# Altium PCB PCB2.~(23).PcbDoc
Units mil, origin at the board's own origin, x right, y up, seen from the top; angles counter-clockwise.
Board outline 7005 x 4320 mil, 2 copper layers (Top Layer, Bottom Layer); 81 components, 33 nets, 200 pads, 0 vias.
Unrouted connection lines stored in the file: 56.
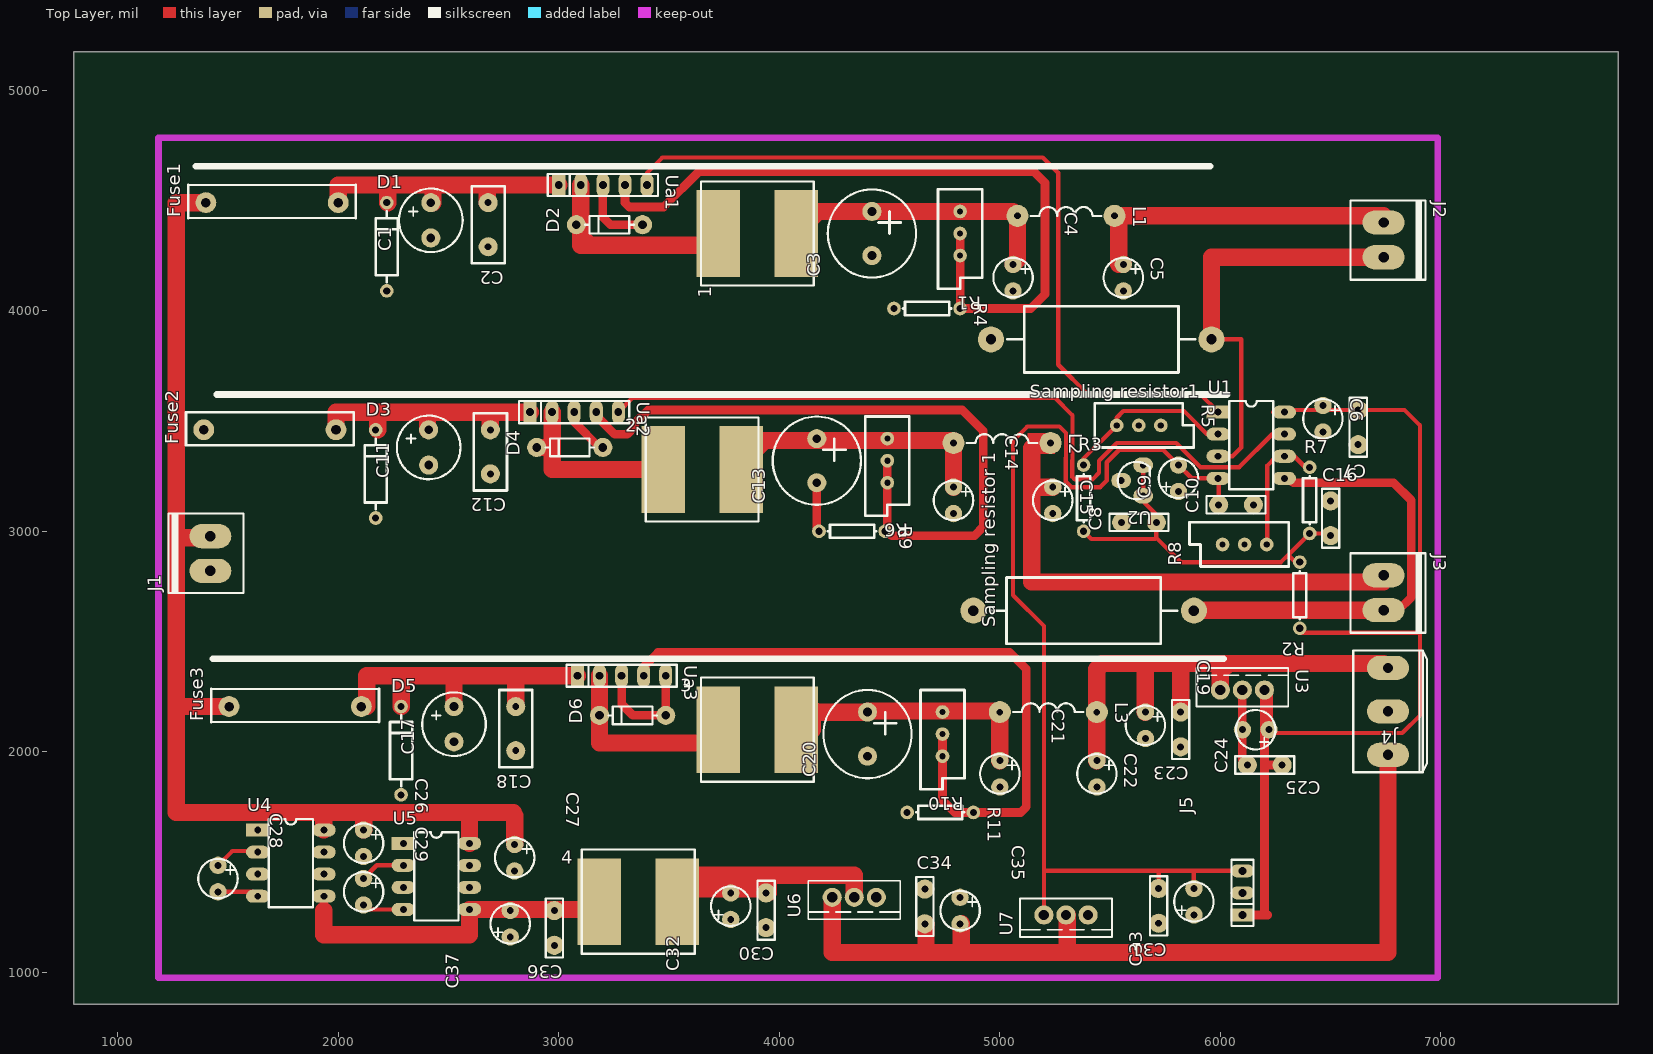
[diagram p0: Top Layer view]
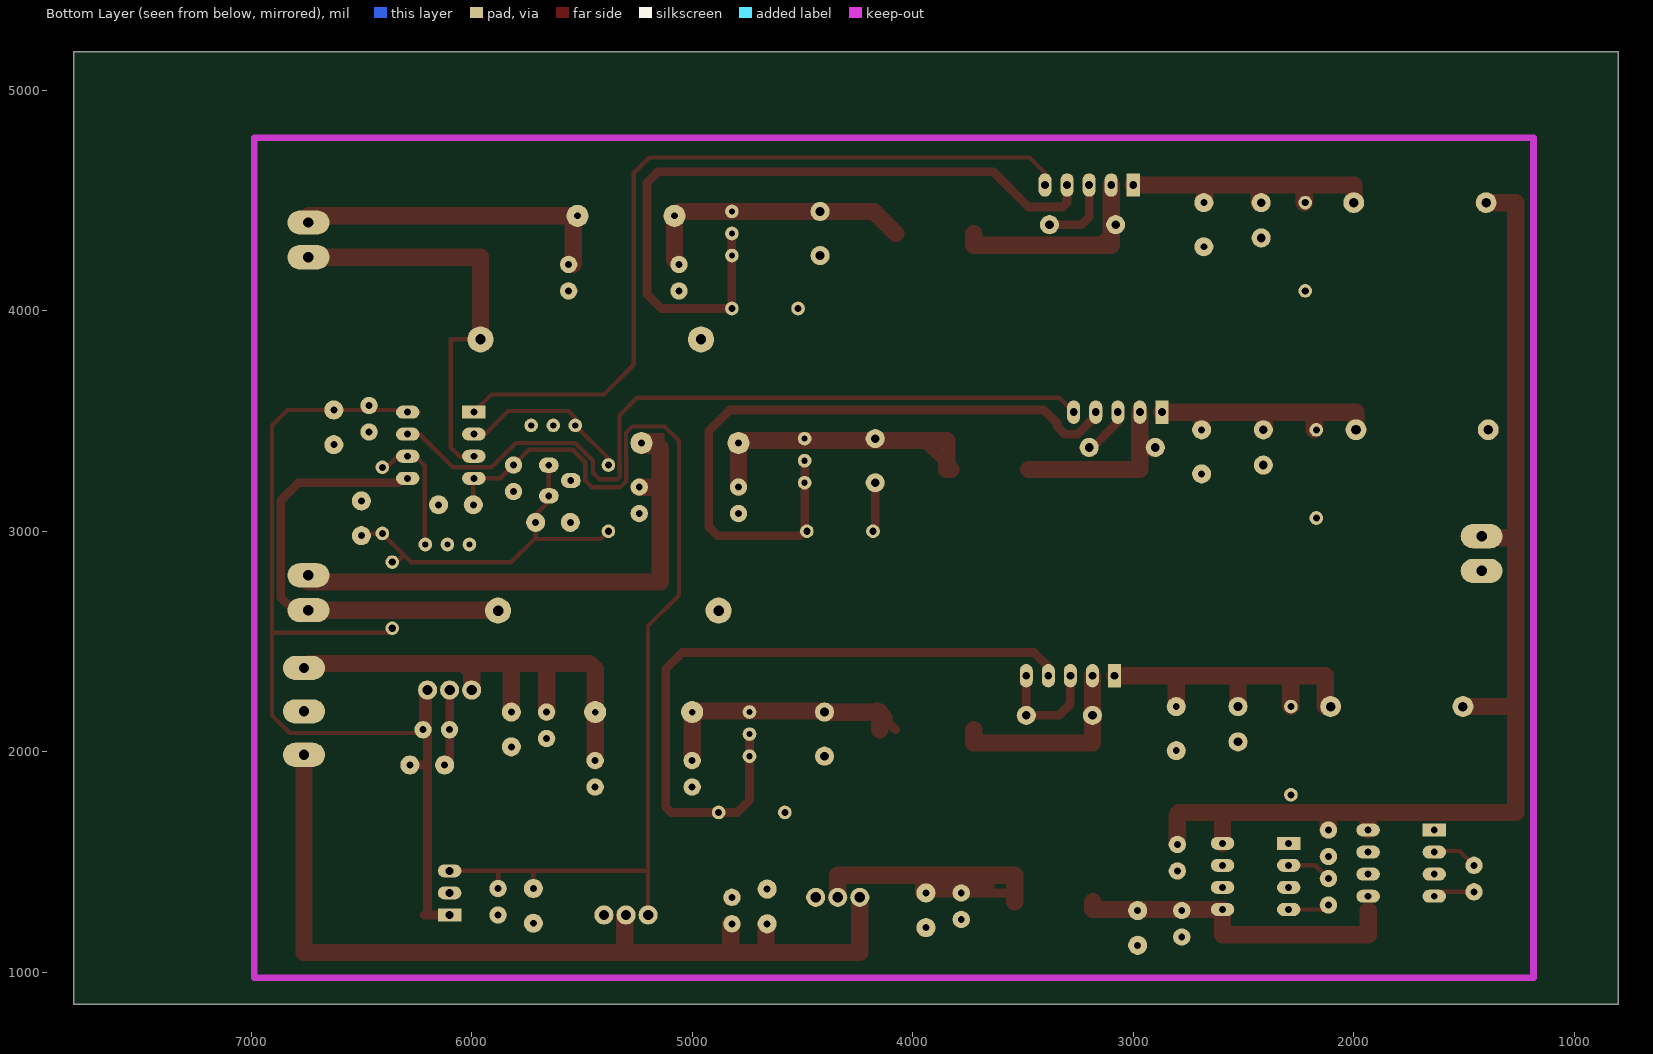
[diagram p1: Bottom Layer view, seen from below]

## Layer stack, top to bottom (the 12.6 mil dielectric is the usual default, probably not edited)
Top Layer: signal copper 1.4
Dielectric: dielectric 12.6, FR-4, Dk 4.8
Bottom Layer: signal copper 1.4

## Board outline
800,5175 800,855 3655,855 7805,855 7805,1010 7805,5175 800,5175

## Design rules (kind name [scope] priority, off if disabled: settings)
Clearance [All] p1: gap=10
PolygonConnect [All] p1: connectstyle=Relief reliefconductorwidth=10 reliefentries=4 polygonreliefangle="90 Angle"
RoutingVias [All] p1: holewidth=28 width=50 viastyle="Through Hole" minholewidth=28 minwidth=50 maxholewidth=28 maxwidth=50
SilkscreenOverComponentPads [All] p1 off: minsilkscreentomaskgap=10
SolderMaskExpansion [All] p1: expansion=4
TestPointUsage [All] p1: valid=0 allowmultiple=FALSE
Testpoint [All] p1: side=15 testpointundercomponent=TRUE minsize=40 maxsize=100 preferedsize=60 minholesize=0 maxholesize=40 preferedholesize=32 testpointgrid=1 style=1023 order=0123456789
Width Width_1 [All] p1: maxlimit=78.74 minlimit=10 preferedwidth=10 toplayer_minwidth=19.68 toplayer_prefwidth=39.37 bottomlayer_minwidth=39.37 bottomlayer_maxwidth=39.37 bottomlayer_prefwidth=39.37 minimp=50.000000 maximp=50.000000 favimp=50.000000
Width [OnLayer('Top Layer')] p2: maxlimit=47.24 minlimit=10 preferedwidth=10 toplayer_minwidth=19.68 toplayer_prefwidth=39.37 bottomlayer_maxwidth=10 minimp=50.000000 maximp=50.000000 favimp=50.000000
23 further rules are at their usual default settings.

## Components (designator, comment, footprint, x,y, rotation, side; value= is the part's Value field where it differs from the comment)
1 "330uh" L 3920,4350 r90 top
2 "330uh" L 3670,3280 r90 top
3 "330uh" L 3920,2100 r90 top
4 "330uh" L 3380,1320 r90 top
C1 "1000uf" RB2 2400,4490 r90 top
C2 "104" RAD0.2 2680,4490 r270 top
C3 "2000uh" RB3 4420,4450 r90 top
C4 "100uf" RB1 5060,4150 r270 top
C5 "100uf" RB1 5560,4150 r270 top
C6 "10uf" RB1 6465,3510 r270 top
C7 "104" RAD0.15 6625,3550 r270 top
C8 "104" RAD0.15 5710,3040 r180 top
C9 "10uf" RB1 5810,3240 r90 top
C10 "104" RAD0.15 6150,3120 r180 top
C11 "1000uf" RB2 2390,3460 r90 top
C12 "104" RAD0.2 2690,3460 r270 top
C13 "2000uf" RB3 4170,3420 r90 top
C14 "100uf3" RB1 4790,3140 r270 top
C15 "100" RB1 5240,3140 r270 top
C16 "104" RAD0.15 6500,2980 r90 top
C17 "1000uf" RB2 2505,2205 r90 top
C18 "104" RAD0.2 2805,2205 r270 top
C19 "10uf" RB1 5660,2120 r270 top
C20 "2000uf" RB3 4400,2180 r90 top
C21 "100uf" RB1 5000,1900 r270 top
C22 "100uf" RB1 5440,1900 r270 top
C23 "104" RAD0.15 5820,2180 r270 top
C24 "104" RAD0.15 6280,1940 r180 top
C25 "10uf" RB1 6160,2100 r180 top
C26 "100uf" RB1 2115,1585 r270 top
C27 "100uf" RB1 2800,1520 r270 top
C28 "10uf" RB1 1455,1425 r270 top
C29 "10uf" RB1 2115,1365 r270 top
C30 "104" RAD0.15 3940,1360 r270 top
C31 "104" RAD0.15 5720,1380 r270 top
C32 "10uf" RB1 3780,1300 r90 top
C33 "10uf" RB1 5880,1320 r90 top
C34 "104" RAD0.15 4660,1220 r90 top
C35 "10uf" RB1 4820,1280 r270 top
C36 "104" RAD0.15 2980,1280 r270 top
C37 "10uf" RB1 2780,1220 r90 top
D1 "IN4007" DIODE0.4 2220,4090 r90 top
D2 "MBR360" DIODE0.2 3260,4390 r180 top
D3 "IN4007" DIODE0.4 2170,3060 r90 top
D4 "MBR360" DIODE0.2 3080,3380 r180 top
D5 "IN4007" DIODE0.4 2285,1805 r90 top
D6 "MBR360" DIODE0.2 3365,2165 r180 top
Fuse1 "4A" RAD0.5 1700,4490 r180 top
Fuse2 "4A" RAD0.5 1690,3460 r180 top
Fuse3 "4A" RAD0.5 1805,2205 r180 top
J1 "CON2" BCON2 1420,2820 r90 top
J2 "CON2" BCON2 6740,4400 r270 top
J3 "CON2" BCON2 6740,2800 r270 top
J4 "CON3" BCON3 6760,2380 r270 top
J5 "CON3" sip-3 6100,1260 r90 top
L1 "20uh" LHF440 5080,4430 r0 top
L2 "20uh" LHF440 4790,3400 r0 top
L3 "20uh" LHF440 5000,2180 r0 top
R1 "50K" VR5 4820,4450 r270 top
R2 "1k" AXIAL0.3 6360,2860 r270 top
R3 "1k" AXIAL0.3 5380,3000 r90 top
R4 "1.21K" AXIAL0.3 4520,4010 r0 top
R5 "5k" VR5 5530,3480 r0 top
R6 "50k" VR5 4490,3420 r270 top
R7 "1k" AXIAL0.3 6405,2990 r90 top
R8 "5k" VR5 6210,2940 r180 top
R9 "1.21K" AXIAL0.3 4180,3000 r0 top
R10 "50k" VR5 4740,2180 r270 top
R11 "1.21k" AXIAL0.3 4580,1725 r0 top
"Sampling resistor1" "0.1" AXIAL1.0 5960,3870 r180 top
"Sampling resistor 1" "0.1   100w" AXIAL1.0 5880,2640 r180 top
U1 "OPA2228" DIP-8 5990,3540 r0 top
U2 "TL431" TO92B 5650,3160 r180 top
U3 "7805" TO257V 6000,2280 r0 top
U4 "ICL7662" DIP-8 1635,1645 r0 top
U5 "ICL7662" DIP-8 2295,1585 r0 top
U6 "7915" TO257V 4440,1340 r180 top
U7 "7905" TO257V 5400,1260 r180 top
Ua1 "LM2596HVADJ" SIP-5 3000,4570 r0 top
Ua2 "LM2596HVADJ" SIP-5 2870,3540 r0 top
Ua3 "LM2596HVADJ" SIP-5 3085,2345 r0 top

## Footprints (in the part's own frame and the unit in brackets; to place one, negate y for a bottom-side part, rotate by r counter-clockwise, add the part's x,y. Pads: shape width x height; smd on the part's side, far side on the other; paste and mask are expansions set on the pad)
AXIAL0.3 [mil]
  round 62 hole 32: 1(0,0) 2(300,0)
  silkscreen extent 41,-30 259,30
AXIAL1.0 [mm]
  round 3 hole 1.2: 1(0,0) 2(25.4,0)
  silkscreen extent 1.91,-3.81 23.49,3.81
BCON2 [mil]
  oval 110x190 hole 47.24: 1(0,0) 2(157.48,0)
  silkscreen extent -100,-150 260,190
BCON3 [mil]
  oval 110x190 hole 47.24: 1(0,0) 2(196.85,0) 3(393.7,0)
  silkscreen extent -79,-157 472,177
DIODE0.2 [mm]
  round 2.2 hole 1: 1(-3.048,0) 2(4.572,0)
  silkscreen extent -2.03,-1.02 3.56,1.02
DIODE0.4 [mil]
  round 62 hole 32: 1(0,0) 2(400,0)
  silkscreen extent 40,-50 360,50
DIP-8 [mm]
  rect 2.7x1.5 hole 0.8: 1(0,0)
  oval 2.7x1.5 hole 0.8: 2(0,-2.54) 3(0,-5.08) 4(0,-7.62) 5(7.62,-7.62) 6(7.62,-5.08) 7(7.62,-2.54) 8(7.62,0)
  silkscreen extent 1.27,-8.89 6.35,1.27
L [mm]
  rect 10x5 smd: 1(0,5) 2(0,-4)
  silkscreen extent -6,-6 6,7
LHF440 [mil]
  round 100 hole 30: 1(0,0) 2(440,0)
  silkscreen extent 60,0 380,40
RAD0.2 [mm]
  round 2.2 hole 0.8: 1(0,0) 2(5.08,0)
  silkscreen extent -1.91,-1.91 6.98,1.91
RAD0.5 [mm]
  round 2.4 hole 1.1: 1(-7.62,0) 2(7.62,0)
  silkscreen extent -9.65,-2.03 9.65,1.78
RAD0.15 [mm]
  round 2.2 hole 0.8: 1(0,0) 2(4,0)
  silkscreen extent -1.4,-1 5.4,1
RB1 [mm]
  round 2 hole 0.8: 1(-1.524,0) 2(1.524,0)
  silkscreen extent -2.27,-2.27 2.27,2.27
RB2 [mm]
  round 2.2 hole 1: 1(0,-0.508) 2(-4.064,-0.508)
  silkscreen extent -5.69,-4.17 1.63,3.15
RB3 [mm]
  round 2.2 hole 1: 1(0,0) 2(-5.08,0)
  silkscreen extent -7.62,-5.08 2.54,5.08
sip-3 [mm]
  rect 1.5x2.7 hole 0.9: 1(0,0)
  oval 1.5x2.7 hole 0.9: 2(2.54,0) 3(5.08,0)
  silkscreen extent -1.27,-1.27 6.35,1.27
SIP-5 [mm]
  rect 1.5x2.7 hole 0.9: 1(0,0)
  oval 1.5x2.7 hole 0.9: 2(2.54,0) 3(5.08,0) 4(7.62,0) 5(10.16,0)
  silkscreen extent -1.27,-1.27 11.43,1.27
TO92B [mil]
  oval 90x70 hole 30: 1(0,0) 2(100,-70) 3(0,-140)
  silkscreen extent -30,-155 115,15
TO257V [mm]
  round 2.2 hole 1.2: 1(0,0) 2(2.54,0) 3(5.08,0)
  silkscreen extent -2.75,-1.91 7.83,2.54
VR5 [mil]
  round 62 hole 28: 1(0,0) 2(100,0) 3(200,0)
  silkscreen extent -100,-100 350,100

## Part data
1 2 3 4: library part INDUCTOR2
C1 C3 C4 C5 C6 C9 C11 C13 C14 C15 C17 C19 C20 C21 C22 C25 C26 C27 C28 C29 C32 C33 C35 C37: library part CAP3
C2 C7 C8 C10 C12 C16 C18 C23 C24 C30 C31 C34 C36: library part CAP1
D1 D2 D3 D4 D5 D6: library part DIODE
Fuse1 Fuse2 Fuse3: library part FUSE1, "Fuse"
J1 J2 J3 J4 J5: "Connector"
L1 L2 L3: library part INDUCTOR
R1 R5 R6 R8 R10: library part RPOT2, "Potentiometer"
R2 R3 R4 R7 R9 R11 "Sampling resistor1" "Sampling resistor 1": library part RES
U1: library part NE5532
U2: "Programmable Voltage Reference"
U3: library part 78**
U6 U7: library part 79**
Ua1 Ua2 Ua3: library part LM2596T-5.0, "Simple Switcher Power Converter 150 kHz 3A Step Down Voltage Regulator"

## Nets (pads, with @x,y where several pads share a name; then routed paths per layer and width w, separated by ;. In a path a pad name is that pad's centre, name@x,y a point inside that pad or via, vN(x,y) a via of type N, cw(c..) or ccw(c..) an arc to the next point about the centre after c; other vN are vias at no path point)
"5V 3A": C5.1 J2.1 L1.2 | length 2868.3
  Top Layer w39.37: L1.2 J2.1@6710,4430 ; L1.2@5540,4410 5540,4230 C5.1
  Top Layer w78.74: C5.1 5540,4210 5540,4430 6740,4430 J2.1
"8V 3A": C15.1 J3.1 L2.2 | length 2326.7
  Top Layer w78.74: 5145,3376.71 5145,3200 ; C15.1 5145,3200 ; J3.1 6740,2770 5145,2770 5145,3200
+5V: C6.1 C7.1 C24.1 C25.1 J5.1 R2.2 U1.8 U3.3 | length 4661.6
  Top Layer w19.68: C25.1 6235,2085 6825,2085 6905,2165 6905,3480 6835,3550 C7.1 U1.8@6300,3550 ; U1.8@6240,3540 U1.8 ; R2.2@6360,2540 6895,2540
  Top Layer w39.37: J5.1 6200,1260 ; 6215,1260 6200,1260 ; C25.1 6220,2260 U3.3 6200,1940 ; C24.1 6200,1940 ; 6200,1260 6200,1940
+15V: C19.1 C22.1 C23.1 J4.1 L3.2 U3.1 | length 2293.1
  Top Layer w78.74: C22.1 L3.2 5440,2375 5465,2400 6035,2400 ; C19.1 5660,2370 ; C23.1 5820,2395 ; U3.1 6000,2365 6035,2400 ; J4.1 6740,2400 6035,2400
-5V: C9.2 C10.2 C31.1 C33.2 J5.3 U1.4 U7.3 | length 4801.9
  Top Layer w19.68: U7.3@5200,1300 U7.3 5200,1460 ; C31.1 5720,1460 ; C33.2 5880,1460 ; C10.2 5992.52,3237.48 U1.4 5870,3240 C9.2 5740,3370 5541.98,3370 5485,3313.02 5485,3230 5455,3200 5325,3200 5299.47,3225.53 5299.47,3333.36 5299.84,3333.73 5299.84,3445.16 5270,3475 5125,3475 5060,3410 5060,2710 5200,2570 5200,1460 ; J5.3 5880,1460 ; 5200,1460 5720,1460 ; 5720,1460 5880,1460
-15V: C34.1 C35.2 J4.3 U6.3 U7.2 | length 4370.4
  Top Layer w39.37: 4660,1145 C34.1 ; 4820,1145 C35.2 ; U7.2 5305,1255 5310,1250 5310,1140
  Top Layer w78.74: U6.3 4240,1090 4665,1090 ; C34.1@4665,1220 4665,1090 ; C35.2@4825,1220 4825,1090 ; U7.2@5305,1260 5305,1255 5305,1090 ; J4.3 6760,1090 5305,1090 ; 4665,1090 4825,1090 ; 4825,1090 5305,1090
FB5V: U1.1 Ua1.5 | length 3662
  Top Layer w19.68: Ua1.5 3400,4625 3470,4695 5195,4695 5265,4625 5265,3755 5400,3620 5910,3620 U1.1
FB8V: U1.7 Ua2.5 | length 3572.8
  Top Layer w19.68: Ua2.5 3335,3605 5250,3605 5329.53,3525.47 5329.53,3321.43 5329.16,3321.06 5329.16,3245.84 5340,3235 5420,3235 5450,3265 5450,3320 5530,3400 5800,3400 5910,3290 6085,3290 6235,3440 U1.7
GND: "Sampling resistor1.2" "Sampling resistor 1.2" C1.2 C2.2 C3.2 C4.2 C5.2 C6.2 C7.2 C8.2 C9.1 C10.1 C11.2 C12.2 C13.2 C14.2 C15.2 C16.2 C17.2 C18.2 C19.2 C20.2 C21.2 C22.2 C23.2 C24.2 C25.2 C26.2 C27.2 C30.2 C31.2 C32.1 C33.1 C34.2 C35.1 C36.2 C37.1 D1.1 D2.1 D3.1 D4.1 D5.1 D6.1 J1.1 J4.2 J5.2 R4.1 R5.2 R5.3 R8.2 R8.3 R9.1 R11.1 U2.2 U3.2 U4.3 U5.3 U6.1 U7.1 Ua1.3 Ua2.3 Ua3.3 Ua3.5 | length 1662.2
  Top Layer w39.37: Ua2.3 3070,3495 3185,3380 D4.1@3210,3380 ; Ua1.3 3200,4425 3235,4390 D2.1 ; Ua3.3 3285,2215 3335,2165 D6.1 Ua3.5 ; R9.1@4170,3010 C13.2 ; U3.2 C25.2 6100,1962.52 C24.2
Net1_1: 1.1 D2.2 Ua1.2 | length 1605.2
  Top Layer w39.37: D2.2@3100,4365 3147.99,4317.01 3690.16,4317.01 1.1
  Top Layer w78.74: Ua1.2 3100,4297.32 3723.15,4297.32 1.1
Net1_2: 1.2 C3.1 C4.1 L1.1 R1.1 | length 1280.5
  Top Layer w78.74: 1.2 4177.48,4450 C3.1 R1.1 5060,4450 L1.1 5080,4230 C4.1
Net2_1: 2.1 D4.2 Ua2.2 | length 833.2
  Top Layer w78.74: D4.2 2970,3380 ; Ua2.2 2970,3380 ; 2.1 2970,3280 2970,3380
Net2_2: 2.2 C13.1 C14.1 L2.1 R6.1 | length 2305.5
  Top Layer w39.37: 2.2 3967.48,3420 C13.1 R6.1 L2.1@4770,3420
  Top Layer w78.74: 2.2 3845,3280 3845,3411.26 4490,3411.26 4790,3411.26 L2.1 C14.1
Net3_1: 3.1 D6.2 Ua3.2 | length 903.2
  Top Layer w78.74: Ua3.2 D6.2 3185,2040 3723.15,2040 3.1
Net3_2: 3.2 C20.1 C21.1 L3.1 R10.1 | length 1328.5
  Top Layer w39.37: 3.2 4130,2152.52 4130,2165 4150,2185 3.2@4162.48,2185
  Top Layer w78.74: 3.2@4130,2152.52 3.2@4162.48,2185 ; 3.2@4150,2100 4150,2180 C20.1 ; C20.1@4400,2185 5000,2185 L3.1 C21.1
Net4_1: 4.1 C36.1 C37.2 U4.5 U5.5 | length 1741.3
  Top Layer w39.37: 1935,1280 1935,1315 U4.5 ; C36.1@2980,1285 4.1@3148.15,1285
  Top Layer w78.74: 1935,1280 1935,1170 2595,1170 U5.5 2980,1285 3183.15,1285 4.1
Net4_2: 4.2 C30.1 C32.2 U6.2 | length 1475
  Top Layer w39.37: 4.2@3577.48,1360 C32.2 C30.1 C30.1@3950,1360
  Top Layer w78.74: 4.2 3537.48,1440 3765,1440 3950,1440 ; C30.1@3950,1360 3950,1440 ; U6.2 4340,1440 3950,1440
NetC1_1: C1.1 C2.1 D1.2 Fuse1.1 Ua1.1 | length 1320
  Top Layer w78.74: Fuse1.1 2000,4570 2225,4570 ; D1.2@2225,4490 2225,4570 ; C1.1@2430,4490 2430,4570 ; C2.1@2675,4490 2675,4570 ; Ua1.1 2675,4570 ; 2225,4570 2430,4570 ; 2430,4570 2675,4570
NetC8_1: C8.1 C16.1 R2.1 R3.1 R7.1 U2.1 U2.3 | length 1655.1
  Top Layer w19.68: R3.1 5415,2965 5705,2965 5710,2970 ; U2.3 U2.1 5650,3135 5710,3075 5710,2970 ; R2.1@6360,2840 6307.5,2892.5 ; C16.1@6490,2990 R7.1 6307.5,2892.5 ; 5710,2970 5820,2860 6275,2860 6307.5,2892.5
NetC11_1: C11.1 C12.1 D3.2 Fuse2.1 Ua2.1 | length 1200
  Top Layer w78.74: Fuse2.1 1990,3540 2180,3540 ; D3.2@2180,3460 2180,3540 ; C11.1@2405,3460 2405,3540 ; C12.1 2690,3540 ; Ua2.1 2690,3540 ; 2180,3540 2405,3540 ; 2405,3540 2690,3540
NetC17_1: C17.1 C18.1 D5.2 Fuse3.1 Ua3.1 | length 1540
  Top Layer w78.74: Fuse3.1 2130,2205 2130,2345 2285,2345 ; D5.2 2285,2345 ; C17.1 2525,2345 ; C18.1 2805,2345 ; Ua3.1 2805,2345 ; 2285,2345 2525,2345 ; 2525,2345 2805,2345
NetC26_1: C26.1 C27.1 Fuse1.2 Fuse2.2 Fuse3.2 J1.2 U4.8 U5.8 | length 5246.4
  Top Layer w78.74: J1.2@1390,2977.48 1390,2970 1265,2970 ; Fuse1.2 1265,4490 1265,2970 ; Fuse3.2 1265,2205 ; U4.8 1935,1724.63 ; C26.1 2115,1724.63 ; U5.8 2595,1724.63 ; 2795,1710 2795,1724.63 2595,1724.63 ; C27.1 2800,1710 ; 1265,2205 1265,2970 ; 1265,2205 1265,1724.63 1935,1724.63 ; 1935,1724.63 2115,1724.63 ; 2115,1724.63 2595,1724.63
NetC28_1: C28.1 U4.2 | length 209
  Top Layer w19.68: C28.1 1520,1550 1630,1550 U4.2
NetC28_2: C28.2 U4.4 | length 160
  Top Layer w19.68: C28.2 U4.4@1615,1365
NetC29_1: C29.1 U5.2 | length 204.9
  Top Layer w19.68: C29.1 2175,1485 U5.2
NetC29_2: C29.2 U5.4 | length 160
  Top Layer w19.68: C29.2@2135,1285 U5.4
NetJ2_2: "Sampling resistor1.1" J2.2 U1.3 | length 1899.1
  Top Layer w19.68: 5960,3870 6095,3870 6095,3380 6055,3340 U1.3
  Top Layer w78.74: 5960,3870 5960,4242.52 J2.2
NetJ3_2: "Sampling resistor 1.1" J3.2 U1.5 | length 2071.3
  Top Layer w39.37: U1.5 6310,3240 6330,3220 6785,3220 6865,3140 6865,2700 6807.52,2642.52 J3.2 J3.2@6737.52,2645
  Top Layer w78.74: 5880,2640 5880,2642.52 J3.2
NetR1_2: R1.2 R1.3 R4.2 Ua1.4 | length 3337.2
  Top Layer w39.37: Ua1.4 3300,4490 3320,4470 3475,4470 3635,4630 5155,4630 5205,4580 5205,4075 5140,4010 R4.2 R1.3 R1.2
NetR3_2: R3.2 R5.1 U1.2 | length 793.1
  Top Layer w19.68: R3.2 5380,3330 R5.1 5530,3515 5560,3545 5835,3545 5940,3440 U1.2
NetR6_2: R6.2 R6.3 R9.2 Ua2.4 | length 3114.3
  Top Layer w39.37: Ua2.4 3170,3523.23 3253.23,3440 3310,3440 3345.04,3475.04 3345.04,3489.15 3405.89,3550 4830,3550 4925,3455 4925,3020 4885,2980 4510,2980 4490,3000 R6.3 R6.2
NetR7_2: R7.2 R8.1 U1.6 | length 589.4
  Top Layer w19.68: R8.1 6213.15,2943.15 6213.15,3298.15 6255,3340 6335,3340 6385,3290 R7.2
NetR10_2: R10.2 R10.3 R11.2 Ua3.4 | length 3171.1
  Top Layer w39.37: Ua3.4 3385,2385 3450,2450 5045,2450 5120,2375 5120,1750 5095,1725 R11.2 4795,1725 4740,1780 R10.3 R10.2
pads on no net: U4.1 U4.6 U4.7 U5.1 U5.6 U5.7

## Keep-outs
Keep-Out Layer:
  lines w30: 1220,4785 6985,4785 6985,975 1185,975 1185,4785 1420,4785

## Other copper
Top Layer:
  rectangle net "8V 3A": 5125,3350 5250,3445
  rectangle net Net4_2: 3630,1340 3960,1480

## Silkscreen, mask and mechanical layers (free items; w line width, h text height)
Top Overlay:
  lines w30: 1355,4655 5955,4655 ; 1430.52,2422.5 6015.52,2422.5 ; 1450,3620 6030,3620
